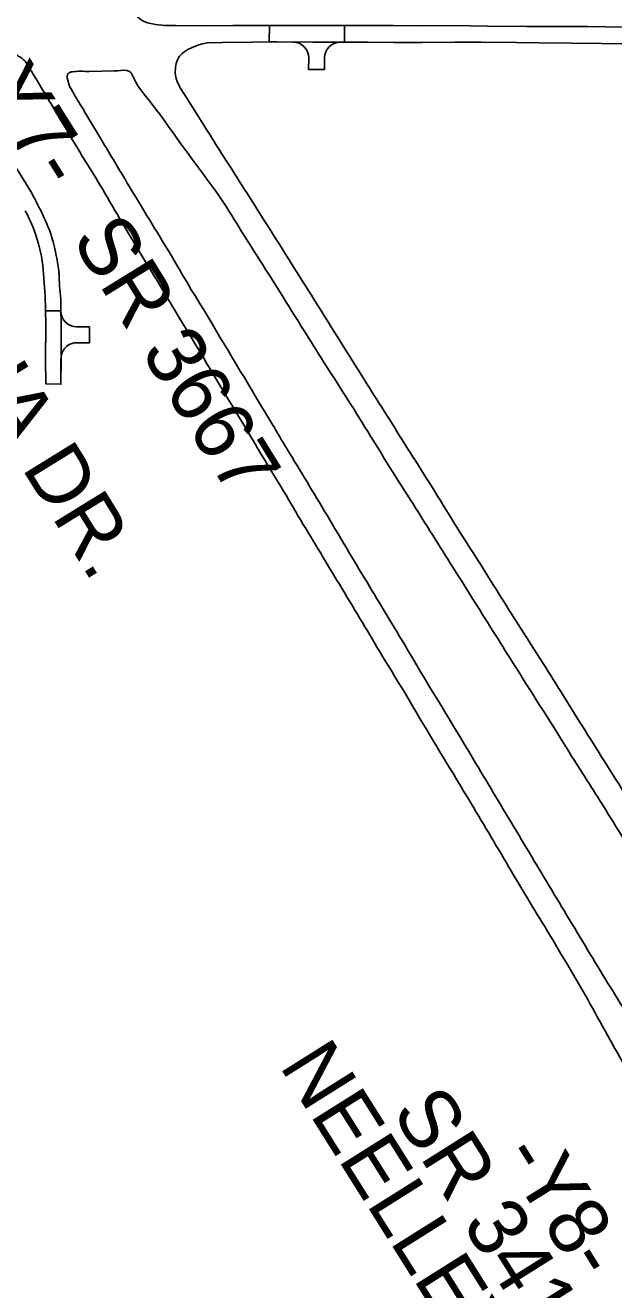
# Model space of a CAD drawing. Extents: x 1750583 to 1791140, y 783580 to 827376.
# Drawn here: x 1780394 to 1781139, y 814121 to 815720 of the extents above; entities that cross this region are included whole.
import ezdxf

# ---------------------------------------------------------------- set-up
doc = ezdxf.new("R2010")
doc.units = 0
for name, color, linetype in [('Exist CMT EOP', 7, 'Continuous'), ('Prop Dimension Text', 7, 'Continuous'), ('Prop EOT', 7, 'Continuous'), ('Prop Shade Heavy', 7, 'Continuous')]:
    doc.layers.add(name, color=color, linetype=linetype)

msp = doc.modelspace()

# ---------------------------------------------------------------- linework, layer by layer
at = {"layer": 'Exist CMT EOP'}
for p, q in [((1780397.7, 815669.5), (1780394.6, 815674.5)), ((1780475.2, 815661.8), (1780506.7, 815662.6)), ((1780514.1, 815475.4), (1780541.5, 815429.5)), ((1780419.4, 815378), (1780417.8, 815399.9))]:
    msp.add_line(p, q, dxfattribs=at)
for points in [[(1780825.4, 815719.9), (1780786.5, 815719.8), (1780741.3, 815720), (1780700.1, 815719.8), (1780656.8, 815719.8), (1780615.4, 815719.7), (1780584.9, 815720)], [(1781282.5, 815717.8), (1781234.9, 815717.3), (1781192.4, 815717.9), (1781151.6, 815718), (1781106, 815718.6), (1781072.4, 815718.7), (1781028.1, 815718.8), (1780978.4, 815719.1), (1780936.2, 815719.8), (1780888.9, 815719.5), (1780859.7, 815719.8), (1780825.4, 815719.9)], [(1780624.3, 815698.1), (1780643.7, 815698.5), (1780682.2, 815699.1), (1780713, 815699.2), (1780758.2, 815698.9), (1780796.2, 815699), (1780827.4, 815699), (1780860.6, 815698.4)], [(1780860.6, 815698.4), (1780896.3, 815698.5), (1780937.3, 815699), (1780971.2, 815698.8), (1781015.8, 815698.5), (1781043.7, 815698), (1781085.4, 815697.8), (1781123, 815697.4), (1781165.2, 815697), (1781204.4, 815696.8), (1781247.9, 815696.4), (1781286.5, 815696.1), (1781325.7, 815696.2)], [(1780623.7, 815588.3), (1780612.9, 815605.5), (1780598.5, 815628.2), (1780590.4, 815641.1)], [(1780402.6, 815507.8), (1780385.7, 815535.4), (1780358.4, 815577), (1780334.9, 815613.5)], [(1780568.8, 815445.8), (1780574, 815437), (1780579.1, 815428.6), (1780584.3, 815420), (1780589.2, 815411.5), (1780594.2, 815403.1), (1780599.4, 815394.5), (1780604.3, 815385.9), (1780609.6, 815377.7), (1780614.8, 815369.1), (1780620.1, 815360.5), (1780625.1, 815351.9), (1780630.3, 815343.6), (1780635.4, 815334.8), (1780640.5, 815326), (1780645.6, 815317.7), (1780650.8, 815309.1), (1780655.9, 815300.3), (1780661.1, 815291.6), (1780666.2, 815283.1), (1780671.4, 815274.7), (1780676.6, 815266), (1780681.7, 815257.5), (1780686.8, 815248.9), (1780691.9, 815240.3), (1780697.1, 815231.6), (1780702.3, 815223.1), (1780707.5, 815214.7)], [(1780541.5, 815429.5), (1780546.5, 815421.3), (1780552.1, 815411.8), (1780557.1, 815403.8), (1780562.2, 815395.4), (1780567.3, 815386.8), (1780572.5, 815378.1), (1780577.6, 815369.6), (1780582.7, 815361.1), (1780588, 815352.2), (1780593.3, 815343.7), (1780598.3, 815335.4), (1780603.6, 815326.8), (1780608.7, 815318.1), (1780613.8, 815309.7), (1780619.1, 815300.9), (1780624, 815292.3), (1780629.3, 815283.8), (1780634.4, 815275), (1780639.5, 815266.6), (1780644.8, 815258), (1780649.8, 815249.4), (1780655.1, 815240.7), (1780660, 815232.5), (1780665.1, 815223.9), (1780670.7, 815215.2), (1780675.6, 815206.7), (1780680.8, 815197.9)], [(1780439.1, 815374.2), (1780439.5, 815330.2), (1780439.4, 815266.4), (1780420.4, 815266.7), (1780420, 815298.7), (1780420.2, 815342.8), (1780419.4, 815378)]]:
    msp.add_lwpolyline(points, dxfattribs=at)
for centre, major_axis, ratio, start_param, end_param in [((1780225.5, 815393.3), (175.1, -79.7), 0.999841, 0.461351, 0.927272), ((1780792.2, 815414.3), (-16, -356.9), 0.99448, 4.777349, 4.86968)]:
    msp.add_ellipse(centre, major_axis=major_axis, ratio=ratio, start_param=start_param, end_param=end_param, dxfattribs=at)
for points in [[(1780584.9, 815720), (1780570.7, 815720.1), (1780555.3, 815721.9), (1780547, 815724.2), (1780535.8, 815731.4), (1780527.5, 815740.7)], [(1780590.4, 815641.1), (1780586.6, 815649.1), (1780584.1, 815660), (1780584.8, 815669.5), (1780587.9, 815679), (1780594.9, 815686.4), (1780605.4, 815692.3), (1780616.6, 815696.2), (1780624.3, 815698.1)], [(1780394.6, 815674.5), (1780389.8, 815678.6), (1780385.1, 815681.7), (1780380.6, 815684.5), (1780376, 815686.9), (1780370.9, 815688.8), (1780366.4, 815690.2), (1780360.2, 815691.2), (1780350.7, 815691.3)], [(1780397.7, 815669.5), (1780410.9, 815647.6), (1780439.3, 815600), (1780462.4, 815561.6), (1780468.9, 815550.8), (1780475.6, 815540.2), (1780488.6, 815518.7), (1780514.1, 815475.4)], [(1780568.8, 815445.8), (1780540.8, 815491.9), (1780517.6, 815530.3), (1780489.4, 815577.5), (1780463.7, 815620.2), (1780451.2, 815641.6), (1780450.2, 815643.6), (1780449.6, 815645.6), (1780449, 815647.7), (1780448.5, 815649.8), (1780447.9, 815651.8), (1780447.3, 815653.8), (1780447.1, 815655.8), (1780447.2, 815656.8), (1780447.4, 815657.2), (1780447.6, 815657.7), (1780450.2, 815660.4), (1780453.9, 815661.4), (1780475.2, 815661.8)], [(1780506.7, 815662.6), (1780508.5, 815662.6), (1780522, 815663.3), (1780526.2, 815661.7), (1780532, 815652.7), (1780552.8, 815622.9), (1780582.5, 815582.6), (1780612.4, 815541.3), (1780642.6, 815499.8), (1780667.9, 815459.7), (1780694.7, 815417.2), (1780723.5, 815371.6), (1780749.4, 815330), (1780774.9, 815289.7), (1780802.5, 815246.6), (1780831, 815200.8), (1780854.3, 815163.2), (1780881.3, 815120.6), (1780909.6, 815075.5), (1780935.1, 815035.1), (1780962.6, 814991.4), (1780988.6, 814949.9), (1781014.4, 814909), (1781040.7, 814867.2), (1781067.8, 814824.4), (1781096, 814779.4), (1781125.2, 814733.4), (1781151.1, 814691.5), (1781176.1, 814651.7), (1781204.5, 814606.6), (1781230.2, 814566), (1781256.1, 814524.9), (1781282, 814483.3), (1781310.3, 814438.6), (1781335.3, 814399.1), (1781361.8, 814356.7), (1781382.8, 814322.4), (1781389.5, 814309.4), (1781392.1, 814297.9), (1781391.6, 814294.9)], [(1780623.7, 815588.3), (1780642.6, 815558.3), (1780668.2, 815518.3), (1780696.6, 815473.4), (1780722.8, 815432.2), (1780749.7, 815389.4), (1780775.7, 815347.7), (1780829.6, 815261.7), (1780854.4, 815222.7), (1780881.2, 815179.9), (1780908.8, 815136.4), (1780936.9, 815090.7), (1780962.3, 815050.8), (1780989.7, 815007.3), (1781016, 814965.5), (1781043.2, 814923), (1781068.3, 814883.1), (1781095.4, 814839.7), (1781123.7, 814794.6)], [(1780437, 815405), (1780436.8, 815408.3), (1780436.6, 815409.8), (1780428.1, 815451.6), (1780416.8, 815479.7), (1780402.6, 815507.8)], [(1781302, 814247.2), (1781298.8, 814253.2), (1781270.8, 814297.7), (1781244, 814336.6), (1781214, 814378.2), (1781185.6, 814419.1), (1781159.3, 814463.2), (1781134.1, 814504.4), (1781108.9, 814545.7), (1781082.7, 814589.3), (1781057, 814632), (1781031.9, 814674), (1781005.9, 814717.4), (1780979.7, 814761.2), (1780955.2, 814801.9), (1780928.3, 814846.6), (1780901.1, 814891.7), (1780877.5, 814931.4), (1780851.5, 814974.5), (1780826.6, 815015.9), (1780800.4, 815059.6), (1780772.5, 815106.5), (1780747.5, 815148), (1780722.3, 815189.6), (1780707.5, 815214.7)], [(1780680.8, 815197.9), (1780694, 815175.8), (1780721, 815131.3), (1780745.9, 815089.2), (1780771.1, 815047.4), (1780798.4, 815002.1), (1780824, 814959.6), (1780848.3, 814918.8), (1780874.6, 814875.6), (1780902.1, 814829.2), (1780926, 814789.7), (1780952, 814746.6), (1780977.3, 814704.3), (1781002.8, 814661.4), (1781029.4, 814616.5), (1781054.5, 814575.4), (1781082.1, 814528.8), (1781105.7, 814488.2), (1781130.7, 814443.3), (1781155.8, 814398.5), (1781178.2, 814357.3), (1781202.4, 814313.6), (1781227.3, 814269.7), (1781240.7, 814246.1)], [(1781123.7, 814794.6), (1781151.9, 814749.7), (1781175.4, 814711.9), (1781204, 814667.2), (1781230.1, 814626.4), (1781255.5, 814585.1), (1781282.9, 814541.4), (1781309, 814500.8), (1781338.1, 814453.8), (1781362.4, 814415.7), (1781389.1, 814373.2), (1781417.2, 814328.4), (1781443.8, 814286), (1781469.2, 814245.3), (1781496.3, 814201.9), (1781523.3, 814159.3), (1781551.5, 814114.9), (1781575, 814076.8), (1781602.3, 814034.5), (1781628.7, 813992.4), (1781657.7, 813946.4), (1781683, 813906.2), (1781710.5, 813862.1), (1781734.7, 813823.6), (1781763.1, 813779.2), (1781788.4, 813738.4), (1781814.8, 813696.3), (1781842.4, 813653.4), (1781868.9, 813610.7), (1781895.8, 813568.7), (1781924.4, 813523.6), (1781950.6, 813481.8), (1781976.7, 813442.7), (1782004.4, 813401.4), (1782032, 813360.1), (1782060.8, 813317.5), (1782089.2, 813276.6), (1782119.2, 813233.3), (1782146.2, 813195.7), (1782175.1, 813155.1), (1782204.1, 813115.4), (1782233.2, 813075.7), (1782263.8, 813034.4), (1782294, 812994.3), (1782325, 812953.9), (1782354.4, 812916.2), (1782385, 812877.4), (1782417.2, 812837.3), (1782449.4, 812797.6), (1782479.5, 812761.8), (1782513.2, 812720.7), (1782543, 812685), (1782576.4, 812645.9), (1782608.5, 812608.7), (1782640.7, 812571.4), (1782677.4, 812531), (1782710.3, 812494.7), (1782741.2, 812460.8), (1782775.5, 812424.1), (1782810.1, 812387), (1782844.4, 812350.7), (1782880.7, 812313.2), (1782914.8, 812277.6), (1782949.9, 812242.2), (1782985.1, 812206.9), (1783022.4, 812170.4), (1783054.9, 812138.6), (1783094.7, 812100.5), (1783130, 812066.9), (1783162.7, 812036.2), (1783200.8, 812001.5), (1783239.6, 811966), (1783275.5, 811933.3), (1783312.5, 811900.8)]]:
    msp.add_spline(points, degree=3, dxfattribs=at)
at = {"layer": 'Prop EOT'}
for p, q in [((1780703, 815719.8), (1780702.9, 815699.2)), ((1780703, 815719.8), (1780741.3, 815720)), ((1780741.3, 815720), (1780786.5, 815719.8)), ((1780786.5, 815719.8), (1780798, 815719.9)), ((1780798, 815719.9), (1780797.9, 815699)), ((1780702.9, 815699.2), (1780713, 815699.2)), ((1780713, 815699.2), (1780732.9, 815699.1)), ((1780797.9, 815699), (1780792.8, 815699)), ((1780752.8, 815679), (1780752.7, 815664.5)), ((1780772.7, 815664.4), (1780752.7, 815664.5)), ((1780772.8, 815679.1), (1780772.7, 815664.4)), ((1780420.2, 815342.8), (1780419.8, 815359.1)), ((1780419.8, 815359.1), (1780439.3, 815359)), ((1780439.3, 815359), (1780439.3, 815358.7)), ((1780420, 815298.7), (1780420.2, 815338.5)), ((1780420.2, 815338.5), (1780420.2, 815342.8)), ((1780475.5, 815338.8), (1780459.2, 815338.9)), ((1780475.5, 815338.8), (1780475.4, 815318.8)), ((1780475.4, 815318.8), (1780459.6, 815318.9)), ((1780420, 815298.7), (1780420.4, 815266.7)), ((1780439.5, 815299), (1780439.4, 815266.4)), ((1780420.4, 815266.7), (1780439.4, 815266.4)), ((1780439.4, 815266.4), (1780439.4, 815269))]:
    msp.add_line(p, q, dxfattribs=at)
for centre, start, end in [((1780732.8, 815679.1), 359.7234, 89.6675), ((1780792.8, 815679), 90.0588, 179.7234), ((1780459.3, 815358.9), 179.6998, 269.6998), ((1780459.5, 815298.9), 89.6998, 179.8485)]:
    msp.add_arc(centre, 20, start, end, dxfattribs=at)
at = {"layer": 'Prop Shade Heavy'}
for p, q in [((1780703, 815719.8), (1780702.9, 815699.2)), ((1780741.3, 815720), (1780703, 815719.8)), ((1780786.5, 815719.8), (1780741.3, 815720)), ((1780798, 815719.9), (1780786.5, 815719.8)), ((1780797.9, 815699), (1780798, 815719.9)), ((1780702.9, 815699.2), (1780713, 815699.2)), ((1780713, 815699.2), (1780732.9, 815699.1)), ((1780792.8, 815699), (1780797.9, 815699)), ((1780752.8, 815679), (1780752.7, 815664.5)), ((1780752.7, 815664.5), (1780772.7, 815664.4)), ((1780772.7, 815664.4), (1780772.8, 815679.1)), ((1780439.3, 815359), (1780419.8, 815359.1)), ((1780419.8, 815359.1), (1780420.2, 815342.8)), ((1780420.2, 815338.5), (1780420, 815298.7)), ((1780420.2, 815342.8), (1780420.2, 815338.5)), ((1780475.5, 815338.8), (1780459.2, 815338.9)), ((1780475.4, 815318.8), (1780475.5, 815338.8)), ((1780459.6, 815318.9), (1780475.4, 815318.8)), ((1780420, 815298.7), (1780420.4, 815266.7)), ((1780420.4, 815266.7), (1780439.4, 815266.4))]:
    msp.add_line(p, q, dxfattribs=at)
msp.add_lwpolyline([(1780439.4, 815266.4), (1780439.4, 815269), (1780439.5, 815299)], dxfattribs=at)
for centre, start, end in [((1780732.8, 815679.1), 359.7234, 89.6675), ((1780792.8, 815679), 90.0588, 179.7234), ((1780459.3, 815358.9), 179.6998, 269.6998), ((1780459.5, 815298.9), 89.6998, 179.8485)]:
    msp.add_arc(centre, 20, start, end, dxfattribs=at)

# ---------------------------------------------------------------- texts
at = {"layer": 'Prop Dimension Text'}
for s, rotation, p in [('-Y7-', 302.0944, (1780317.2, 815670.1)), ('BEGONIA DR.', 301.7096, (1780134.2, 815573.4)), ('SR 3667', 301.7096, (1780451.8, 815449.9)), ('NEELLEY RD.', 302.1612, (1780714.9, 814404.6)), ('SR 3418', 302.2047, (1780856.9, 814346.4)), ('-Y8-', 301.9187, (1780994.8, 814291.2))]:
    msp.add_text(s, height=75, rotation=rotation, dxfattribs=at).set_placement(p)

doc.saveas('drawing.dxf')
